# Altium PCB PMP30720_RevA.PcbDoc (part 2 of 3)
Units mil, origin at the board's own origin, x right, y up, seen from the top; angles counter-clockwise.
Board outline 4575 x 5400 mil, 4 copper layers (Top Layer, Signal Layer 1, Signal Layer 2, Bottom Layer), stack 61.6 mil thick; 223 components, 107 nets, 514 pads, 63 vias.
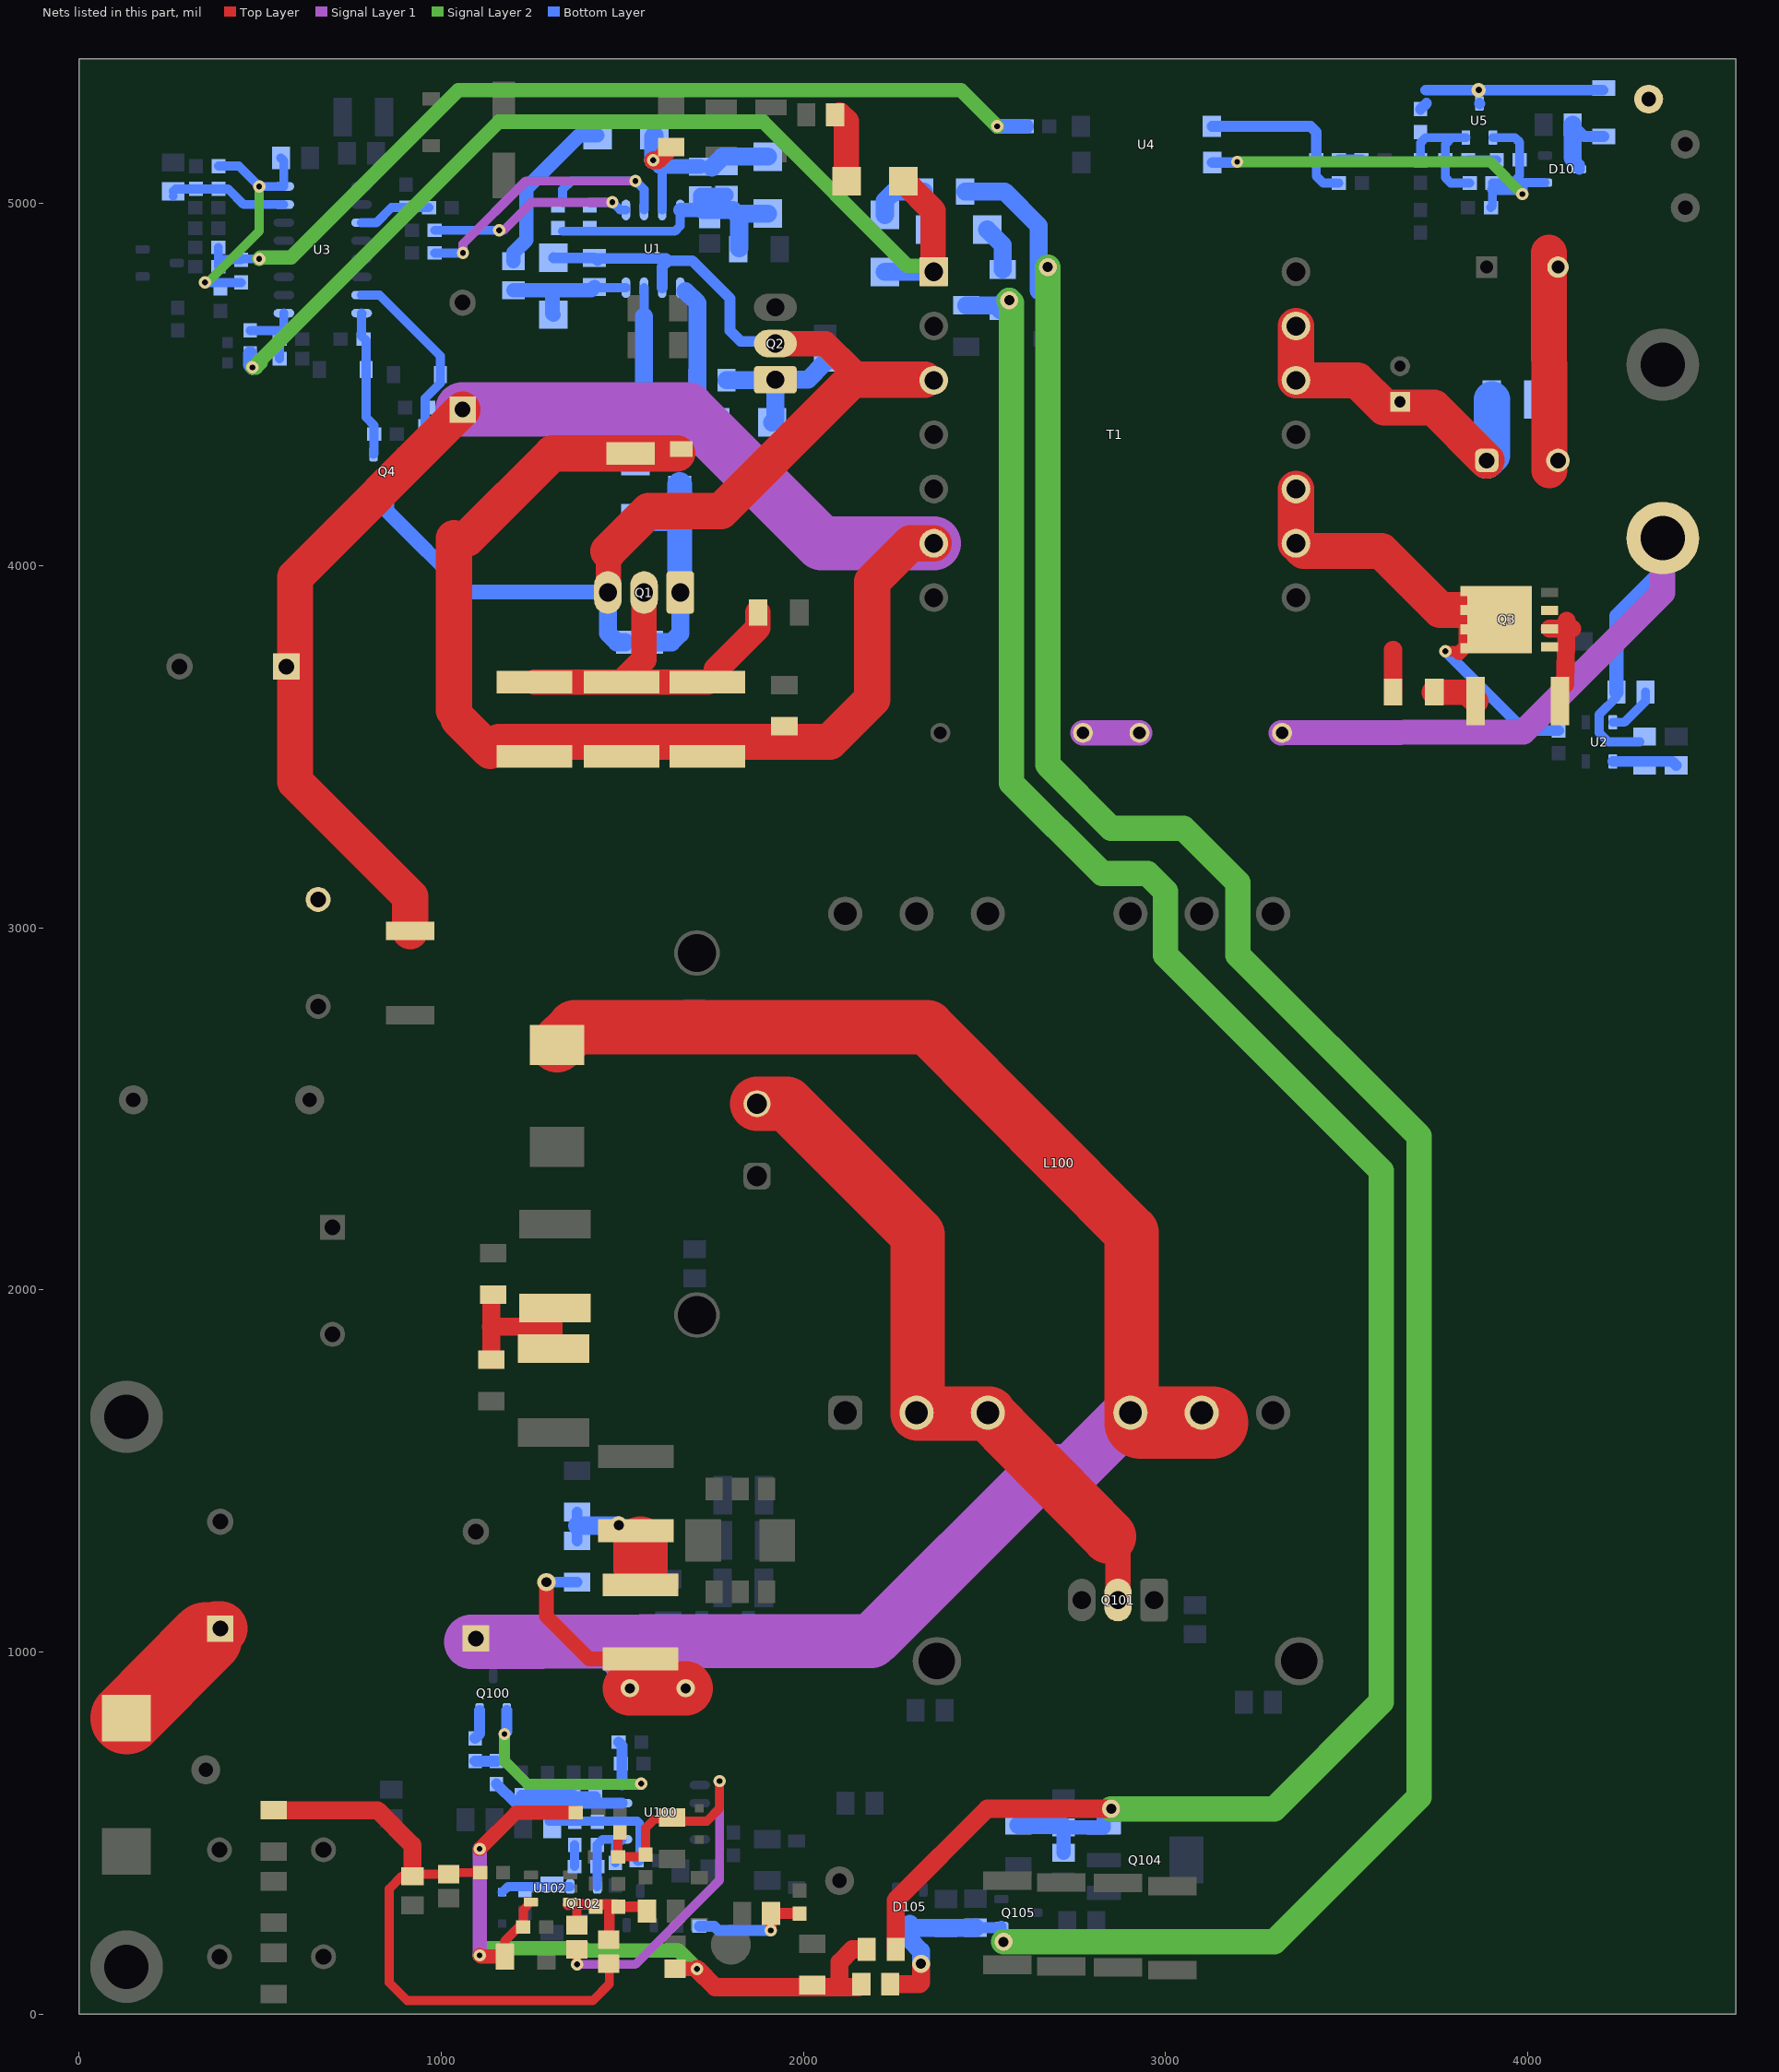
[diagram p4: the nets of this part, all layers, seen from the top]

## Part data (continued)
C102 C104 C124: library part Capacitor, "CAP, CERM, xxxF, xxV, [TempCo], xx%, [PackageReference]", Alternate Manufacturer=-, Manufacturer="Used in BOM report"
C103 C106: "CAP, CERM, 2.2 µF, 250 V,+/- 20%, X7R, AEC-Q200 Grade 1, 6x5x5mm", Cap_Case=2220, Manufacturer=TDK, Supplier Part Number 1=445-4110-1-ND, TempCo=X7R, Tolerance_%=20, Value2=250V, ValueDisplayed=2.2µF
C105: library part CMP-0010026-1, "CAP, AL, 47 uF, 400 V, +/- 20%, TH", Cap_Case=18x20, Manufacturer=Panasonic, Supplier Part Number 1=P13667-ND, Tolerance_%=20%, Value1=Unknown, Value2=400V, ValueDisplayed=47uF
C107: "CAP, CERM, 0.1 µF, 50 V,+/- 10%, X7R, 0603", Cap_Case=0603, Manufacturer=MuRata, Supplier Part Number 1=490-4779-1-ND, TempCo=X7R, Tolerance_%=10, Value1="0.02 ohm", Value2=50V, ValueDisplayed=0.1µF
C108: "CAP, CERM, 2.2 µF, 25 V,+/- 10%, X7R, 1206", Cap_Case=1206, Manufacturer=MuRata, Supplier Part Number 1=490-3368-1-ND, TempCo=X7R, Tolerance_%=10, Value2=25V, ValueDisplayed=2.2µF
C109: library part C0603C103J5RACTU, "CAP, CERM, 0.01 µF, 50 V,+/- 5%, X7R, 0603", Cap_Case=0603, Manufacturer=Kemet, Supplier Part Number 1=399-1092-1-ND, TempCo=X7R, Tolerance_%=5, Value2=50V
C110: "CAP, CERM, 0.47 µF, 50 V,+/- 10%, X7R, 0603", Cap_Case=0603, Manufacturer=TDK, Supplier Part Number 1=445-5952-1-ND, TempCo=X7R, Tolerance_%=10, Value1="0.010974 ohm", Value2=50V, ValueDisplayed=0.47µF
C111: "CAP, CERM, 47 pF, 50 V,+/- 5%, C0G/NP0, 0603", Cap_Case=0603, Manufacturer=MuRata, Supplier Part Number 1=490-1419-1-ND, TempCo=C0G/NP0, Tolerance_%=5, Value2=50V, ValueDisplayed=47pF
C112: "CAP, CERM, 470 pF, 50 V,+/- 5%, C0G/NP0, 0603", Cap_Case=0603, Manufacturer=MuRata, Supplier Part Number 1=490-1443-1-ND, TempCo=C0G/NP0, Tolerance_%=5, Value2=50V, ValueDisplayed=470pF
C113: "CAP, CERM, 1 µF, 16 V,+/- 10%, X7R, 0805", Cap_Case=0805, Manufacturer=MuRata, Supplier Part Number 1=490-1691-1-ND, TempCo=X7R, Tolerance_%=10, Value1="0.003 ohm", Value2=16V, ValueDisplayed=1µF
C114: "CAP, CERM, 4.7 µF, 25 V,+/- 10%, X7R, 1206", Cap_Case=1206, Manufacturer=MuRata, Supplier Part Number 1=490-1809-1-ND, TempCo=X7R, Tolerance_%=10, Value2=25V, ValueDisplayed=4.7µF
C116: "CAP, CERM, 0.1 µF, 50 V,+/- 10%, X7R, 0603", Cap_Case=0603, Manufacturer=MuRata, Supplier Part Number 1=490-1519-1-ND, TempCo=X7R, Tolerance_%=10, Value2=50V, ValueDisplayed=0.1µF
C120: "CAP, CERM, 0.22 µF, 50 V,+/- 10%, X7R, 0805", Cap_Case=0805, Manufacturer=MuRata, Supplier Part Number 1=490-1670-1-ND, TempCo=X7R, Tolerance_%=10, Value2=50V, ValueDisplayed=0.22µF
C121: library part Capacitor, "CAP, CERM, xxxF, xxV, [TempCo], xx%, [PackageReference]", Alternate Manufacturer=-
D1: "Diode, Ultrafast, 600 V, 1 A, AEC-Q101, SMA", Manufacturer="ON Semiconductor", Supplier Part Number 1=MURA160T3GOSCT-ND, Value1=1A, Value2=1.05V
D2 D5: "Diode, Schottky, 30 V, 1 A, SMA", Manufacturer="Diodes Inc.", Supplier Part Number 1=B130-FDICT-ND, Value1=1A, Value2=0.5V
D3 D4: "Diode, Zener, 18 V, 1 W, AEC-Q101, SMA", Manufacturer="Diodes Inc.", Power_W=1, Supplier Part Number 1=SMAZ18-FDICT-ND, Value1=1W
D6 D7: "Diode, Ultrafast, 200 V, 1 A, SMA", Manufacturer="Diodes Inc.", Supplier Part Number 1=ES1D-FDICT-ND, Value1=1A, Value2=0.92V
D8: "Diode, Schottky, 200 V, 1 A, SMA", Manufacturer="Micro Commercial Components", Supplier Part Number 1=SS1200-LTPMSCT-ND, Value1=1A, Value2=0.92V
D9: "Diode, Zener, 27 V, 500 mW, SOD-123", Manufacturer="Diodes Inc.", Power_W=0.5, Supplier Part Number 1=MMSZ5254B-FDICT-ND, Value1=0.5W
D10: "Diode, Schottky, 30 V, 0.2 A, SOT-23", Manufacturer="Diodes Inc.", Supplier Part Number 1=BAT54S-FDICT-ND, Value1=0.2A, Value2=0.65V
D100: "Diode, Switching, 800 V, 3 A, SMC", Manufacturer=Vishay-Semiconductor, Supplier Part Number 1=RS3K-E3/9ATGICT-ND, Value1=3A, Value2=1.3V
D101: library part APT20SCD65K, "Diode, Schottky, 600 V,", Manufacturer=Microsemi
D102 Dz2: "Diode, Zener, 18 V, 500 mW, SOD-123", Manufacturer="Diodes Inc.", Power_W=0.5, Supplier Part Number 1=MMSZ5248B-FDICT-ND, Value1=0.5W
D103: "Diode, Schottky, 30 V, 0.2 A, SOD-323", Manufacturer="ON Semiconductor", Supplier Part Number 1=BAT54HT1OSCT-ND, Value1=0.2A, Value2=0.35V
D104: "Diode, Schottky, 20 V, 0.5 A, SOD-123", Manufacturer="ON Semiconductor", Supplier Part Number 1=MBR0520LT1GOSCT-ND, Value1=0.5A, Value2=0.385V
D105: "Diode, Zener, 18 V, 225 mW, SOT-23", Manufacturer="ON Semiconductor", Power_W=0.225, Supplier Part Number 1=MMBZ5248BLT1GOSCT-ND, Value1=0.225W
D106: "Diode, Zener, 10 V, 200 mW, SOD-323", Manufacturer="Diodes Inc.", Power_W=0.2, Supplier Part Number 1=MMSZ5240BS-FDICT-ND, Value1=0.2W
D107: "Diode, Zener, 4.7 V, 500 mW, SOD-123", Manufacturer="ON Semiconductor", Power_W=0.5, Supplier Part Number 1=MMSZ4688T1GOSCT-ND, Value1=0.5W
"DANGER HIGH VOLTAGE1" "High Voltage100": library part IEC_HighVoltage, "IEC 61010-1 High Voltage Warning"
DZ1: "Diode, Zener, 24 V, 500 mW, SOD-123", Manufacturer="Diodes Inc.", Power_W=0.5, Supplier Part Number 1=MMSZ5252B-FDICT-ND, Value1=0.5W
F100: library part 0443003.DR, "Fuse, 5 A, 250VAC/VDC, SMD", Irating_A=5, Manufacturer=Littelfuse, Supplier Part Number 1=F2910CT-ND
H100: "HEATSINK TO-220 W/PINS 1\" TALL", Manufacturer=Aavid, Supplier Part Number 1=HS351-ND
H101: "Heatsink, TO-220, TO-218, TO-247", Manufacturer=Ohmite, Supplier Part Number 1=FA-T220-64E-ND
L1: library part CMP-0064179-1, "Inductor, Unshielded Drum Core, Ferrite, 1 uH, 8 A, 0.006 ohm, TH", Manufacturer="Wurth Elektronik", Supplier Part Number 1=732-2565-ND, Value1="0.006 ohm", Value2=8A, ValueDisplayed=SHORT
L100: library part CMP-0086236-1, "Inductor, 300 µH, 0.065 ohm, TH", Manufacturer="Wurth Elektronik", Value1="0.065 ohm", Value2=A, ValueDisplayed=300µH
Q1 Q2: library part MOSFET_N_D2G1S3, "MOSFET, N-CH, 650V, xxxA, [PackageReference]", Alternate Manufacturer=-, Manufacturer=Infineon
Q3: library part CMP-0079124-1, "MOSFET, N-CH, 200 V, PG-TDSON-8", Alternate Manufacturer=None, PartNumber=SiR616DP, Supplier Part Number 1=SiR610DP, Value1="? ohm"
Q4: "MOSFET, N-CH, 600 V, 0.021 A, AEC-Q101, SOT-23", Alternate Manufacturer=None, Manufacturer="Infineon Technologies", Supplier Part Number 1="BSS126 H6906CT-ND", Value1="? ohm", Value2="1.4 nC"
Q5: library part CMP-0000769-1, "MOSFET, N-CH, 60 V, 0.17 A, SOT-23", Alternate Manufacturer=None, Manufacturer="Diodes Inc.", Supplier Part Number 1=2N7002-FDICT-ND, Value1=7, Value2="223 nC"
Q100 Q103: library part "MMBT3904-7-F, Diodes Inc.", "Transistor, NPN, 40 V, 0.2 A, SOT-23", Manufacturer="Diodes Inc.", Supplier Part Number 1=MMBT3904-FDICT-ND, Value1="0.2 A", Value2=400
Q101: library part CMP-0001173-3, "MOSFET, N-CH, 600 V, 25 A, TO-220AB", Alternate Manufacturer=None, Manufacturer="Infineon Technologies", Supplier Part Number 1=IPP60R125C, Value2="53 nC"
Q102: library part "MMBT2907ALT1G, ON Semiconductor", "Transistor, PNP, 60 V, 0.6 A, SOT-23", Manufacturer="ON Semiconductor", Supplier Part Number 1=MMBT2907ALT1GOSCT-ND, Value1="0.6 A"
Q104: library part CMP-0086195-1, "MOSFET, N-CH, Depletion Mode, 600 V, 0.1 A, SOT-223", Alternate Manufacturer=None, Manufacturer=IXYS, Value1="? ohm", Value2="? nC"
Q105: "MOSFET, N-CH, 60 V, 0.17 A, SOT-23", Alternate Manufacturer=None, Manufacturer="Diodes Inc.", Supplier Part Number 1=2N7002-FDICT-ND, Value1="7.5 ohm", Value2="223 nC"
R1 R2: "RES, 383 k, 1%, 0.25 W, 1206", Manufacturer=Vishay-Dale, Power_W=0.25, Supplier Part Number 1=541-383KFCT-ND, TempCo="100 ppm/C", Tolerance_%=1, Value1=1%, Value2=0.25W, Value_Code=383k
R3 R20 R24 R110: "RES, 10, 5%, 0.125 W, 0805", Manufacturer=Vishay-Dale, Power_W=0.125, Supplier Part Number 1=541-10ACT-ND, TempCo="200 ppm/C", Tolerance_%=5, Value1=5%, Value2=0.125W, Value_Code=10R0, ValueDisplayed=10
R4: "RES, 100, 5%, 0.25 W, 1206", Manufacturer=Vishay-Dale, Power_W=0.25, Supplier Part Number 1=541-100ECT-ND, TempCo="200 ppm/C", Tolerance_%=5, Value1=5%, Value2=0.25W, Value_Code=100R, ValueDisplayed=100
R5 R8: "RES, 4.99 k, 1%, 0.125 W, 0805", Manufacturer=Vishay-Dale, Power_W=0.125, Supplier Part Number 1=541-4.99KCCT-ND, TempCo="100 ppm/C", Tolerance_%=1, Value1=1%, Value2=0.125W, Value_Code=4k99, ValueDisplayed=4.99k
R6 R7: "RES, 15.0, 1%, 0.125 W, 0805", Manufacturer=Vishay-Dale, Power_W=0.125, Supplier Part Number 1=541-15.0CCT-ND, TempCo="100 ppm/C", Tolerance_%=1, Value1=1%, Value2=0.125W, Value_Code=15R0, ValueDisplayed=15.0
R9 R40 R102 R104 R151 R152: library part Resistor, "RES, xxx ohm, x%, xW, [PackageReference]", Alternate Manufacturer=-, Manufacturer="Used in BOM report"
R10 R132: "RES, 0, 5%, 0.25 W, 1206", Manufacturer=Vishay-Dale, Power_W=0.25, Supplier Part Number 1=541-0.0ECT-ND, TempCo="200 ppm/C", Tolerance_%=5, Value1=5%, Value2=0.25W, Value_Code=0000, ValueDisplayed=0
R11 R12 R23: "RES, 49.9, 1%, 0.1 W, 0603", Manufacturer=Vishay-Dale, Power_W=0.1, Supplier Part Number 1=541-49.9HCT-ND, TempCo="100 ppm/C", Tolerance_%=1, Value1=1%, Value2=0.1W, Value_Code=49R9, ValueDisplayed=49.9
R13: "RES, 0.27, 1%, 0.25 W, 1206", Manufacturer=Panasonic, Power_W=0.25, Supplier Part Number 1=P.27RCT-ND, TempCo="250 ppm/C", Tolerance_%=1, Value1=1%, Value2=0.25W, Value_Code=R270, ValueDisplayed=0.27
R14: "RES, 0.33, 1%, 0.25 W, 1206", Manufacturer=Panasonic, Power_W=0.25, Supplier Part Number 1=P.33RCT-ND, TempCo="250 ppm/C", Tolerance_%=1, Value1=1%, Value2=0.25W, Value_Code=R330, ValueDisplayed=0.33
R15: "RES, 3.3, 5%, 1 W, AEC-Q200 Grade 0, 2512", Manufacturer=Vishay-Dale, Power_W=1, Supplier Part Number 1=541-3.3XCT-ND, TempCo="200 ppm/C", Tolerance_%=5, Value1=5%, Value2=1W, Value_Code=3R30, ValueDisplayed=3.3
R16: "RES, 499, 1%, 0.25 W, 1206", Manufacturer=Vishay-Dale, Power_W=0.25, Supplier Part Number 1=541-499FCT-ND, TempCo="100 ppm/C", Tolerance_%=1, Value1=1%, Value2=0.25W, Value_Code=499R, ValueDisplayed=499
R17: "RES, 10.0, 1%, 0.25 W, 1206", Manufacturer=Vishay-Dale, Power_W=0.25, Supplier Part Number 1=541-10.0FCT-ND, TempCo="100 ppm/C", Tolerance_%=1, Value1=1%, Value2=0.25W, Value_Code=10R0, ValueDisplayed=10.0
R18: "RES, 10.0, 1%, 0.125 W, 0805", Manufacturer=Vishay-Dale, Power_W=0.125, Supplier Part Number 1=541-10.0CCT-ND, TempCo="100 ppm/C", Tolerance_%=1, Value1=1%, Value2=0.125W, Value_Code=10R0, ValueDisplayed=10.0
R19: "RES, 10.0, 1%, 0.1 W, 0603", Manufacturer=Vishay-Dale, Power_W=0.1, Supplier Part Number 1=541-10.0HCT-ND, TempCo="100 ppm/C", Tolerance_%=1, Value1=1%, Value2=0.1W, Value_Code=10R0, ValueDisplayed=10.0
R21: "RES, 41.2 k, 1%, 0.1 W, 0603", Manufacturer=Vishay-Dale, Power_W=0.1, Supplier Part Number 1=541-41.2KHCT-ND, TempCo="100 ppm/C", Tolerance_%=1, Value1=1%, Value2=0.1W, Value_Code=41k2, ValueDisplayed=41.2k
R22 R109: "RES, 10.0 k, 1%, 0.1 W, 0603", Manufacturer=Vishay-Dale, Power_W=0.1, Supplier Part Number 1=541-10.0KHCT-ND, TempCo="100 ppm/C", Tolerance_%=1, Value1=1%, Value2=0.1W, Value_Code=10k0, ValueDisplayed=10.0k
R25 R115 R119 R144 R147: "RES, 0, 5%, 0.1 W, 0603", Manufacturer=Vishay-Dale, Power_W=0.1, Supplier Part Number 1=541-0.0GCT-ND, TempCo="200 ppm/C", Tolerance_%=5, Value1=5%, Value2=0.1W, Value_Code=0000, ValueDisplayed=0
R26: "RES, 1.00 M, 1%, 0.1 W, 0603", Manufacturer=Vishay-Dale, Power_W=0.1, Supplier Part Number 1=541-1.00MHCT-ND, TempCo="100 ppm/C", Tolerance_%=1, Value1=1%, Value2=0.1W, Value_Code=1M00, ValueDisplayed=1.00M
R27: "RES, 196 k, 1%, 0.1 W, 0603", Manufacturer=Vishay-Dale, Power_W=0.1, Supplier Part Number 1=541-196KHCT-ND, TempCo="100 ppm/C", Tolerance_%=1, Value1=1%, Value2=0.1W, Value_Code=196k
R28 R29: "RES, 1.00 k, 1%, 0.1 W, 0603", Manufacturer=Vishay-Dale, Power_W=0.1, Supplier Part Number 1=541-1.00KHCT-ND, TempCo="100 ppm/C", Tolerance_%=1, Value1=1%, Value2=0.1W, Value_Code=1k00, ValueDisplayed=1.00k
R30: "RES, 34.0 k, 1%, 0.1 W, 0603", Manufacturer=Vishay-Dale, Power_W=0.1, Supplier Part Number 1=541-34.0KHCT-ND, TempCo="100 ppm/C", Tolerance_%=1, Value1=1%, Value2=0.1W, Value_Code=34k0, ValueDisplayed=34.0k
R31: "RES, 12.1 k, 1%, 0.1 W, 0603", Manufacturer="Yageo America", Power_W=0.1, Supplier Part Number 1=311-12.1KHRCT-ND, TempCo="200 ppm/C", Tolerance_%=1, Value1=1%, Value2=0.1W, Value_Code=12k1, ValueDisplayed=12.1k
R32 R36: "RES, 150 k, 1%, 0.1 W, 0603", Manufacturer=Vishay-Dale, Power_W=0.1, Supplier Part Number 1=541-150KHCT-ND, TempCo="100 ppm/C", Tolerance_%=1, Value1=1%, Value2=0.1W, Value_Code=150k
R33: "RES, 15.0 k, 1%, 0.1 W, 0603", Manufacturer=Vishay-Dale, Power_W=0.1, Supplier Part Number 1=541-15.0KHCT-ND, TempCo="100 ppm/C", Tolerance_%=1, Value1=1%, Value2=0.1W, Value_Code=15k0, ValueDisplayed=15.0k
R34: "RES, 121, 1%, 0.1 W, 0603", Manufacturer=Vishay-Dale, Power_W=0.1, Supplier Part Number 1=541-121HCT-ND, TempCo="100 ppm/C", Tolerance_%=1, Value1=1%, Value2=0.1W, Value_Code=121R, ValueDisplayed=121
R35: "RES, 604 k, 1%, 0.1 W, 0603", Manufacturer=Vishay-Dale, Power_W=0.1, Supplier Part Number 1=541-604KHCT-ND, TempCo="100 ppm/C", Tolerance_%=1, Value1=1%, Value2=0.1W, Value_Code=604k
R37 R121 R138: "RES, 249 k, 1%, 0.1 W, 0603", Manufacturer=Vishay-Dale, Power_W=0.1, Supplier Part Number 1=541-249KHCT-ND, TempCo="100 ppm/C", Tolerance_%=1, Value1=1%, Value2=0.1W, Value_Code=249k
R38: "RES, 124 k, 1%, 0.1 W, 0603", Manufacturer=Vishay-Dale, Power_W=0.1, Supplier Part Number 1=541-124KHCT-ND, TempCo="100 ppm/C", Tolerance_%=1, Value1=1%, Value2=0.1W, Value_Code=124k
R39: "RES, 47.5 k, 1%, 0.1 W, 0603", Manufacturer=Vishay-Dale, Power_W=0.1, Supplier Part Number 1=541-47.5KHCT-ND, TempCo="100 ppm/C", Tolerance_%=1, Value1=1%, Value2=0.1W, Value_Code=47k5, ValueDisplayed=47.5k
R41: "RES, 21.5 k, 1%, 0.1 W, 0603", Manufacturer=Vishay-Dale, Power_W=0.1, Supplier Part Number 1=541-21.5KHCT-ND, TempCo="100 ppm/C", Tolerance_%=1, Value1=1%, Value2=0.1W, Value_Code=21k5, ValueDisplayed=21.5k
R42: "RES, 100 k, 1%, 0.125 W, 0805", Manufacturer=Vishay-Dale, Power_W=0.125, Supplier Part Number 1=541-100KCCT-ND, TempCo="100 ppm/C", Tolerance_%=1, Value1=1%, Value2=0.125W, Value_Code=100k
R100 R101 R116 R117 R134 R146: "RES, 0, 5%, 0.125 W, 0805", Manufacturer=Vishay-Dale, Power_W=0.125, Supplier Part Number 1=541-0.0ACT-ND, TempCo="200 ppm/C", Tolerance_%=5, Value1=5%, Value2=0.125W, Value_Code=0000, ValueDisplayed=0
R103 R106: "RES, 499 k, 1%, 0.25 W, 1206", Manufacturer=Vishay-Dale, Power_W=0.25, Supplier Part Number 1=541-499KFCT-ND, TempCo="100 ppm/C", Tolerance_%=1, Value1=1%, Value2=0.25W, Value_Code=499k
R105: "RES, 49.9, 1%, 0.125 W, 0805", Manufacturer=Vishay-Dale, Power_W=0.125, Supplier Part Number 1=541-49.9CCT-ND, TempCo="100 ppm/C", Tolerance_%=1, Value1=1%, Value2=0.125W, Value_Code=49R9, ValueDisplayed=49.9
R107 R108: "RES, 374 k, 1%, 0.125 W, 0805", Manufacturer=Vishay-Dale, Power_W=0.125, Supplier Part Number 1=541-374KCCT-ND, TempCo="100 ppm/C", Tolerance_%=1, Value1=1%, Value2=0.125W, Value_Code=374k
R111: "RES, 30.1 k, 1%, 0.1 W, 0603", Manufacturer=Vishay-Dale, Power_W=0.1, Supplier Part Number 1=541-30.1KHCT-ND, TempCo="100 ppm/C", Tolerance_%=1, Value1=1%, Value2=0.1W, Value_Code=30k1, ValueDisplayed=30.1k
R112 R118 R123 R130: "RES, 4.7 k, 5%, 1 W, AEC-Q200 Grade 0, 2512", Manufacturer=Vishay-Dale, Power_W=1, Supplier Part Number 1=541-4.7KXCT-ND, TempCo="200 ppm/C", Tolerance_%=5, Value1=5%, Value2=1W, Value_Code=4k70, ValueDisplayed=4.7k
R113 R145: "RES, 10.0 k, 1%, 0.125 W, 0805", Manufacturer=Vishay-Dale, Power_W=0.125, Supplier Part Number 1=541-10.0KCCT-ND, TempCo="100 ppm/C", Tolerance_%=1, Value1=1%, Value2=0.125W, Value_Code=10k0, ValueDisplayed=10.0k
R114: "RES, 6.98 k, 1%, 0.1 W, 0603", Manufacturer=Vishay-Dale, Power_W=0.1, Supplier Part Number 1=541-6.98KHCT-ND, TempCo="100 ppm/C", Tolerance_%=1, Value1=1%, Value2=0.1W, Value_Code=6k98, ValueDisplayed=6.98k
R120: library part CRCW06032K21FKEA, "RES, 2.21 k, 1%, 0.1 W, 0603", Manufacturer=Vishay-Dale, Power_W=0.1, Supplier Part Number 1=541-2.21KHCT-ND, TempCo="100 ppm/C", Tolerance_%=1, Value1=1%, Value2=0.1W, Value_Code=2k21
R122: "RES, 19.1 k, 1%, 0.1 W, 0603", Manufacturer=Vishay-Dale, Power_W=0.1, Supplier Part Number 1=541-19.1KHCT-ND, TempCo="100 ppm/C", Tolerance_%=1, Value1=1%, Value2=0.1W, Value_Code=19k1, ValueDisplayed=19.1k
R124: "RES, 2.21 k, 1%, 0.1 W, 0603", Manufacturer=Vishay-Dale, Power_W=0.1, Supplier Part Number 1=541-2.21KHCT-ND, TempCo="100 ppm/C", Tolerance_%=1, Value1=1%, Value2=0.1W, Value_Code=2k21, ValueDisplayed=2.21k
R125: library part CRCW060337K4FKEA, "RES, 37.4 k, 1%, 0.1 W, 0603", Manufacturer=Vishay-Dale, Power_W=0.1, Supplier Part Number 1=541-37.4KHCT-ND, TempCo="100 ppm/C", Tolerance_%=1, Value1=1%, Value2=0.1W, Value_Code=37k4
R126: "RES, 4.99, 1%, 0.25 W, 1206", Manufacturer=Vishay-Dale, Power_W=0.25, Supplier Part Number 1=541-4.99FFCT-ND, TempCo="100 ppm/C", Tolerance_%=1, Value1=1%, Value2=0.25W, Value_Code=4R99, ValueDisplayed=4.99
R127 R128 R129: library part Resistor, "RES, 0.18 ohm, 1%, 500mW, current sense [PackageReference]", Alternate Manufacturer=-, Manufacturer="Panasonic Electronic Components"
R131 R133: "RES, 200 k, 5%, 0.125 W, 0805", Manufacturer=Vishay-Dale, Power_W=0.125, Supplier Part Number 1=541-200KACT-ND, TempCo="200 ppm/C", Tolerance_%=5, Value1=5%, Value2=0.125W, Value_Code=200k
R135: library part CRCW08050000Z0EA, "RES, 0, 5%, 0.125 W, 0805", Manufacturer=Vishay-Dale, Power_W=0.125, Supplier Part Number 1=541-0.0ACT-ND, TempCo="200 ppm/C", Tolerance_%=5, Value1=5%, Value2=0.125W, Value_Code=0000
R136: "RES, 0, 5%, 0.333 W, 0805", Manufacturer=Vishay-Dale, Power_W=0.333, Supplier Part Number 1=541-0.0TBCT-ND, TempCo="200 ppm/C", Tolerance_%=5, Value1=5%, Value2=0.333W, Value_Code=0000, ValueDisplayed=0
R137 R140: "RES, 3.92 M, 1%, 0.25 W, 1206", Manufacturer=Vishay-Dale, Power_W=0.25, Supplier Part Number 1=541-3.92MFCT-ND, TempCo="100 ppm/C", Tolerance_%=1, Value1=1%, Value2=0.25W, Value_Code=3M92, ValueDisplayed=3.92M
R139 R142: library part Resistor, "RES, xxx ohm, x%, xW, [PackageReference]", Alternate Manufacturer=-
R141 R149: "RES, 499 k, 1%, 0.1 W, 0603", Manufacturer=Vishay-Dale, Power_W=0.1, Supplier Part Number 1=541-499KHCT-ND, TempCo="100 ppm/C", Tolerance_%=1, Value1=1%, Value2=0.1W, Value_Code=499k
R143: "RES, 499 k, 1%, 0.125 W, 0805", Manufacturer=Vishay-Dale, Power_W=0.125, Supplier Part Number 1=541-499KCCT-ND, TempCo="100 ppm/C", Tolerance_%=1, Value1=1%, Value2=0.125W, Value_Code=499k
R148: "RES, 100 k, 1%, 0.1 W, 0603", Manufacturer=Vishay-Dale, Power_W=0.1, Supplier Part Number 1=541-100KHCT-ND, TempCo="100 ppm/C", Tolerance_%=1, Value1=1%, Value2=0.1W, Value_Code=100k
R150: "RES, 402 k, 1%, 0.125 W, 0805", Manufacturer=Vishay-Dale, Power_W=0.125, Supplier Part Number 1=541-402KCCT-ND, TempCo="100 ppm/C", Tolerance_%=1, Value1=1%, Value2=0.125W, Value_Code=402k
RF1: "RES, 0, 5%, 1 W, AEC-Q200 Grade 0, 2512", Manufacturer=Vishay-Dale, Power_W=1, Supplier Part Number 1=541-0.0XCT-ND, TempCo=ppm/C, Tolerance_%=5, Value1=5%, Value2=1W, Value_Code=0000, ValueDisplayed=0
RT1: library part B57237S0479M000, "Thermistor NTC, 5 ohm", Manufacturer=TDK, Power_W=3.1, Supplier Part Number 1=495-2099-ND, Tolerance_%=20
RT2: "Thermistor NTC, 47.0k ohm, 1%, 0603", Manufacturer=MuRata, Power_W=0.1, Supplier Part Number 1=NCP18WB473F10RB-ND, Tolerance_%=1
RT100 RT101: library part B57237S229M, "Thermistor NTC, 2.2 ohm, 20%, 15x7mm", Manufacturer=TDK, Power_W=3.1, Supplier Part Number 1=495-3055-ND, Tolerance_%=20
T1: library part CMP-0086589-1, "PTH_TRANSFORMER_14", Manufacturer="Wurth Electronics"
TP1 TP2 TP5 TP6: "Test Point, Miniature, Red, TH", Color=Red, Manufacturer=Keystone, Supplier Part Number 1=36-5000-ND
TP3 TP4 TP100 TP102: library part 1503-2, "Terminal, Turret, TH, Double", Manufacturer=Keystone, Supplier Part Number 1=36-1503-2-ND
TP7: "Test Point, Miniature, Black, TH", Color=Black, Manufacturer=Keystone, Supplier Part Number 1=36-5001-ND
TP101: library part CMP-0055137-1, "Test Point, Miniature, Red, TH", Color=Red, Manufacturer=Keystone, Supplier Part Number 1=36-5000-ND
TP103: library part CMP-0055138-1, "Test Point, Miniature, Black, TH", Color=Black, Manufacturer=Keystone, Supplier Part Number 1=36-5001-ND
TP104: "PC Test Point, SMT", Manufacturer=Mill-Max, Supplier Part Number 1=ED1088CT-ND
U1: library part CMP-0013005-1, "620-V High-Side Low-Side Gate Driver with 2.5A Peak Output and RobustDrive, D0008A (SOIC-8)", Alternate Manufacturer="Texas Instruments", Alternate PartNumber=UCC27712D
U2: library part CMP-0013050-3, "High-Frequency Multi-Mode Synchronous Rectifier Controller, DBV0005A (SOT-23-5)", Alternate Manufacturer="Texas Instruments", Alternate PartNumber=UCC24612-1DBVT
U3: library part CMP-0013027-1, "Active-Clamp Flyback Controller, D0016A (SOIC-16)", Alternate Manufacturer="Texas Instruments", Alternate PartNumber=UCC28780D
U4: "Optocoupler, 5 kV, 80-160% CTR, SMT", Manufacturer="Fairchild Semiconductor", Supplier Part Number 1=FOD817AS-ND, Voltage_Isolation_Vrms=5000V
U5: library part CMP-0066200-1, "2.5V Low Iq Adjustable Precision Shunt Regulator, DBZ0003A (SOT-23-3)", Alternate Manufacturer="Texas Instruments", Alternate PartNumber=ATL431BQDBZT
U100: "BiCMOS Low Current 8 Pin PWM Current Mode Controller, D0008A (SOIC-8)", Alternate Manufacturer="Texas Instruments", Alternate PartNumber=UCC28C42D
U101: library part CMP-0078944-1, "Transformer, 500 uH, SMD", Manufacturer="Wurth Elektronik", Supplier Part Number 1=732-3282-1-ND, ValueDisplayed=500µH
U102: library part CMP-0080757-2, "40 V, microPower, Push-Pull Comparator with Shutdown, DBV0006A (SOT-23-6)", Alternate Manufacturer="Texas Instruments"

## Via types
v1: diameter 34, hole 16, Top Layer to Bottom Layer, 36 vias
v2: diameter 50, hole 28, Top Layer to Bottom Layer, 21 vias
v3: diameter 40, hole 18, Top Layer to Bottom Layer, 5 vias
v4: diameter 32, hole 16, Top Layer to Bottom Layer, 1 vias

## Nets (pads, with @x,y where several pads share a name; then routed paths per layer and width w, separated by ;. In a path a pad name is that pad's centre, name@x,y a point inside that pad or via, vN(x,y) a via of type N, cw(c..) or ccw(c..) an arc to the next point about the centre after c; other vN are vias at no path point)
AUX_ACF_1: C18.1 C120.1 D105.3 Q105.1 R16.1 R135.2 R143.2 | length 7066.4
  Top Layer w50: R135.2@2240,83.12 2320.62,83.12 2325,87.5 v2(2325,139.32)
  Signal Layer 2 w70: v2(2552.87,200.07) 3300.07,200.07 3700,600 3700,2425 3200,2925 3200,3125 3050,3275 2850,3275 2675,3450 v2(2675,4824.48)
  Bottom Layer w30: R143.2@2475,239.04 2542.43,239.04 Q105.1@2546.51,243.12 2546.51,206.43 v2(2552.87,200.07)
  Bottom Layer w50: v2(2325,139.32) 2325,174.19 2293.75,205.44 D105.3@2293.75,249.13 2304.92,237.96 C120.1@2393.75,237.96 2473.92,237.96 R143.2@2475,239.04 ; R16.1@2446.86,5033.09 2555.6,5033.09 2650,4938.69 C18.1@2650,4760.14
AUX_ACF_2: C17.1 C119.1 Q104.3 R17.1 R133.1 R134.2 R136.2 | length 6572.4
  Top Layer w50: R134.2@2255,179.04 2255,314.69 2507.62,567.31 v2(2850,567.31)
  Signal Layer 2 w70: v2(2568.65,4732.67) 2575,4726.32 2575,3400 2825,3150 2950,3150 3000,3100 3000,2925 3595.72,2329.28 3595.72,862.78 3300.25,567.31 v2(2850,567.31)
  Bottom Layer w40: R133.1@2718.75,446.25 R136.2@2718.75,516.25 2718.87,516.13 Q104.3@2829.58,516.13 2829.58,546.89 v2(2850,567.31)
  Bottom Layer w50: C17.1@2450,4718.87 2535.01,4718.87 R17.1@2550,4703.88 ; C119.1@2593.75,522.05 2712.95,522.05 R136.2@2718.75,516.25
  Bottom Layer w70: R17.1@2550,4714.01 v2(2568.65,4732.67)
Disable: C122.1 R119.2 R146.2 | length 328.8
  Top Layer w30: v1(1910.28,231.25) 1910.62,231.59 R146.2@1910.62,278.44 1989.12,278.44 C122.1@1989.37,278.2
  Bottom Layer w30: R119.2@1712.52,243.02 1753.98,243.02 1765.75,231.25 v1(1910.28,231.25)
FB: C111.2 R108.1 R121.1 R122.2 U100.2 | length 365.3
  Bottom Layer w25: R108.1@1297.73,532.8 U100.2@1499.54,532.8 1541.49,532.8 1548.45,525.84 1548.45,423.64 1541.49,423.64 R122.2@1543.28,421.85
GND1: C13.2 C14.2 C15.2 C22.1 C24.2 C25.2 C39.2 Q3.1 Q3.2 Q3.3 R15.2 R41.1 TP4.1 TP7.1 U2.2 U5.3 | length 3445.8
  Top Layer w50: Q3.2@4060.02,3825.97 4122.22,3825.97 ; R15.2@4103.03,3672.57 4107.36,3847.57
  Top Layer w100: 4058.56,4863.47 4060.02,4263.47
  Signal Layer 1 w70: C22.1@3319.49,3538.47 3987.53,3540.85 4372.64,3925.97 TP4.1@4372.64,4075.97
  Bottom Layer w25: C24.2@4245.14,3650.97 4245.14,3636.83 4197.64,3589.33 U2.2@4197.64,3567.6 4197.64,3538.47 4222.64,3513.47 C25.2@4310.14,3513.47
  Bottom Layer w30: R41.1@3704.13,5260.52 R41.1@3720.38,5276.77 ; 3718.19,5313.47 v3(3864.44,5313.47) C39.2@4207.14,5313.47 ; U5.3@3866.63,5276.77 U5.3@3867.44,5275.97
  Bottom Layer w40: C24.2@4245.14,3650.97 4245.14,3860.97 4372.64,3988.47 TP4.1@4372.64,4075.97
NetC1_1: C1.1 C2.1 C3.1 C4.1 C5.1 C6.1 C7.1 R1.2 RF1.2 RT1.2 T1.6 | length 6109.1
  Top Layer w100: RF1.2@914.3,2991.14 914.3,3085.7 596.54,3403.46 596.54,3968.54 C2.1@1059.04,4431.04 ; 1035.14,3600.97 1035.14,4075.97 ; 1047.64,3575.97 1135.14,3488.47 ; 1072.64,4075.97 1306.4,4309.73 C3.1@1522.64,4309.73 C4.1@1651.51,4309.73 ; 1160.14,3513.47 2072.64,3513.47 2189.93,3630.75 2189.93,3955.75 2295.95,4061.78 T1.6@2360.14,4061.78
  Signal Layer 1 w150: C2.1@1059.04,4431.04 1680.74,4431.04 2050,4061.78 T1.6@2360.14,4061.78
NetC5_2: C5.2 C6.2 C7.2 Q1.2 R2.1 | length 955.7
  Top Layer w70: C7.2@1257.95,3678.33 C6.2@1497.64,3678.33 ; Q1.2@1560.14,3925.97 1560.14,3740.83 C6.2@1497.64,3678.33 ; C5.2@1735.14,3678.33 C6.2@1497.64,3678.33 ; 1760.14,3713.47 1874.81,3828.14 R2.1@1874.81,3870.92
NetC8_1: C8.1 D3.1 R3.1 U1.8 | length 383.7
  Bottom Layer w25: C8.1@1422.64,4768.4 1423.29,4767.75 U1.8@1510.14,4767.75
  Bottom Layer w40: R3.1@1199.81,4760.97 1307.28,4760.97 ; D3.1@1310.14,4693.21 1307.28,4696.07 1307.28,4760.97 ; C8.1@1423.29,4769.51 1414.74,4760.97 1307.28,4760.97
NetC8_2: C8.2 D3.2 Q1.3 Q2.2 Q4.3 R5.1 T1.3 U1.6 | length 3245.7
  Top Layer w70: Q1.3@1460.14,3925.97 1461.67,3927.5 1461.67,4040 ; Q2.2@1922.64,4613.47 2060.14,4613.47 2135.14,4538.47 2135.14,4513.47
  Top Layer w100: 1461.67,4040 1572.64,4150.97 1772.64,4150.97 2135.14,4513.47 T1.3@2335.14,4513.47
  Bottom Layer w25: C8.2@1422.64,4848.4 C8.2@1431.63,4839.41
  Bottom Layer w30: D3.2@1310.14,4850.69 1311.32,4849.51 C8.2@1423.29,4849.51 ; C8.2@1422.64,4848.4 1621.08,4848.4 1627.2,4842.28 ; U1.6@1610.14,4767.75 1610.14,4825.23 1627.2,4842.28 ; Q2.2@1922.64,4613.47 1916.7,4619.41 1826.87,4619.41 1797.64,4648.64 1797.64,4737.89 1693.24,4842.28 1627.2,4842.28
  Bottom Layer w40: Q4.3@850.48,4213.07 850.48,4150.97 1074.3,3927.15 1458.96,3927.15 Q1.3@1460.14,3925.97
  Bottom Layer w50: Q1.3@1460.14,3925.97 1460.14,3813.47 1485.14,3788.47 R5.1@1507.64,3788.47
NetC9_1: C9.1 C10.1 D1.2 D4.1 R4.2 U1.3 | length 661.5
  Top Layer w50: v1(1585.14,5119.57) 1598.33,5119.57 R4.2@1635.14,5156.38
  Bottom Layer w25: D1.2@1588.88,5188.47 1610.14,5167.21 1610.14,5119.57 ; U1.3@1610.14,4982.32 1610.14,5102.28 ; C10.1@1722.64,5100.09 1747.64,5100.09
  Bottom Layer w40: v1(1585.14,5119.57) 1602.42,5102.28 1610.14,5102.28 C10.1@1715.04,5102.28
  Bottom Layer w50: v1(1585.14,5119.57) 1585.14,5184.73 D1.2@1588.88,5188.47 ; 1747.64,5100.09 1776.87,5129.32 D4.1@1901.58,5129.71
NetC9_2: C9.2 C10.2 C11.2 C12.2 D4.2 R9.1 R10.2 U1.4 | length 831.8
  Bottom Layer w25: C12.2@1335.14,4923.47 1645.14,4923.47 1660.14,4938.47 U1.4@1660.14,4982.32
  Bottom Layer w40: U1.4@1660.14,4982.32 1722.25,4982.32 1715.04,4989.52 C10.2@1715.04,5022.28 1716.22,5023.47 C9.2@1787.64,5023.47
  Bottom Layer w50: R9.1@1722.25,4982.32 1804.78,4982.32 1814.88,4972.23 D4.2@1901.58,4972.23 ; R10.2@1822.64,4876.78 1822.64,4971.84
NetC11_1: C11.1 R11.2 U1.1 | length 618.8
  Signal Layer 1 w25: v1@1172.64,4925.97 1250.14,5003.47 v1(1472.64,5003.47)
  Bottom Layer w25: R11.2@982.21,4925.97 v1(1160.14,4925.97) ; C11.1@1410.14,5003.47 v1(1472.64,5003.47) 1493.78,4982.32 U1.1@1510.14,4982.32
NetC12_1: C12.1 R12.2 U1.2 | length 987
  Signal Layer 1 w25: v1(1060.14,4863.47) 1060.14,4888.47 1233.96,5062.28 v1(1536.32,5062.28)
  Bottom Layer w25: R12.2@982.21,4863.47 v1(1060.14,4863.47) ; C12.1@1335.14,5003.47 1335.14,5038.47 1358.96,5062.28 v1(1536.32,5062.28) 1560.14,5038.47 U1.2@1560.14,4982.32
NetC13_1: C13.1 C15.1 L1.1 T1.12 T1.13 | length 942.3
  Top Layer w100: T1.13@3360.14,4661.78 T1.12@3360.14,4511.78 3529.43,4511.78 3604.79,4436.42 3740.93,4436.42 C13.1@3886.71,4290.63
  Bottom Layer w100: C13.1@3886.71,4290.63 3901.1,4305.02 C15.1@3901.1,4458.79
NetC16_1: C16.1 R15.1 | length 124.6
  Top Layer w70: C16.1@3742.22,3650.97 3831.5,3650.97 R15.1@3856.5,3625.97
NetC16_2: C16.2 Q3.5 Q3.6 Q3.7 Q3.8 Q3.9 R19.2 T1.9 T1.10 | length 1319.7
  Top Layer w30: v1(3772.64,3763.47) 3806.93,3763.47 3810.98,3759.41 ; Q3.8@3823.8,3772.23 Q3.7@3823.8,3824.39
  Top Layer w40: 3810.98,3759.41 Q3.8@3823.8,3772.23
  Top Layer w50: C16.2@3628.05,3650.97 3628.05,3767.36
  Top Layer w100: T1.10@3360.14,4211.78 T1.9@3360.14,4061.78 3381.43,4040.49 3595.61,4040.49 3758.56,3877.54 Q3.6@3823.8,3877.54
  Bottom Layer w30: v1(3772.64,3763.47) 3991.14,3544.96 R19.2@4085.14,3544.96
NetC21_1: C21.1 C22.2 | length 156.3
  Signal Layer 1 w70: C21.1@2771.85,3538.47 C22.2@2928.15,3538.47
NetC23_1: C23.1 R21.1 R22.2 U3.9 | length 224.5
  Bottom Layer w25: R21.1@472.64,4649.45 564.18,4649.45 565.7,4650.97 ; C23.1@553.64,4571.5 R22.2@553.64,4625.97 565.7,4638.03 565.7,4650.97 ; U3.9@565.7,4697.34 565.7,4650.97
NetC24_1: C24.1 U2.3 | length 139.3
  Bottom Layer w25: U2.3@4235.04,3567.6 4266.77,3567.6 4325.14,3625.97 C24.1@4325.14,3650.97
NetC25_1: C25.1 R24.1 U2.4 | length 179.6
  Bottom Layer w30: U2.4@4235.04,3459.33 4399.27,3459.33 R24.1@4410.14,3448.47
NetC26_1: C26.1 C28.1 R33.2 R35.2 U3.12 | length 2603.5
  Signal Layer 2 w40: v1(497.64,4847.34) 501.27,4850.97 585.14,4850.97 1047.64,5313.47 2435.14,5313.47 v1(2535.14,5213.47)
  Bottom Layer w25: C28.1@384.62,4878.77 R35.2@384.62,4839.17 ; U3.12@565.7,4847.34 v1(497.64,4847.34) 450.01,4847.34 C26.1@447.64,4844.96 390.4,4844.96 R35.2@384.62,4839.17 ; R35.2@384.62,4839.17 R35.2@384.62,4825.97 R35.2@384.62,4839.17
  Bottom Layer w40: v1(2535.14,5213.47) R33.2@2616.14,5213.47
NetC26_2: C26.2 C31.1 R25.1 R27.1 U3.16 | length 718.2
  Signal Layer 2 w25: v1(347.64,4782.46) 356.52,4782.46 497.64,4923.58 v1(497.64,5047.34)
  Bottom Layer w25: v1(347.64,4782.46) 348.13,4781.97 C26.2@447.64,4781.97 ; R27.1@385.14,5103.46 441.51,5103.46 v1(497.64,5047.34) U3.16@565.7,5047.34 565.7,5117.9 C31.1@557.64,5125.97
NetC27_2: C27.2 DZ1.1 Q4.1 R26.2 U3.8 | length 405.6
  Bottom Layer w25: U3.8@781,4696.6 U3.8@780.27,4697.34 780.27,4634.27 792.52,4622.02 DZ1.1@792.52,4541.77 792.52,4409.63 814.49,4387.65 R26.2@814.49,4363.47 814.49,4308.97 Q4.1@813.08,4307.56
NetC29_1: C29.1 R28.1 | length 62.2
  Bottom Layer w30: C29.1@3479.13,5120.22 3479.54,5120.63 R28.1@3541.14,5120.63
NetC29_2: C29.2 R31.1 U4.1 | length 486.5
  Bottom Layer w25: C29.2@3416.14,5120.22 3416.14,5075.97 3435.33,5056.78 R31.1@3478.64,5056.78
  Bottom Layer w30: U4.1@3128.25,5213.47 3400.21,5213.47 3416.14,5197.53 C29.2@3416.14,5120.22
NetC30_1: C30.1 C33.1 R32.1 R41.2 U5.2 | length 370.2
  Bottom Layer w25: R32.1@3704.13,5120.22 3704.13,5168 3718.41,5182.28 3791.22,5182.28 ; U5.2@3829.23,5182.28 3791.22,5182.28 ; C30.1@3839.64,5056.78 3787.64,5056.78 3772.64,5071.78 C33.1@3772.64,5120.63 3772.64,5163.7 3791.22,5182.28
NetC30_2: C30.2 D10.1 R30.1 R36.1 U4.2 U5.1 | length 1403.2
  Signal Layer 2 w30: v1(3197.64,5115.26) 3895.85,5115.26 v1(3985.14,5025.97)
  Bottom Layer w25: R30.1@3898.13,4988.91 3902.63,4993.41 C30.2@3902.63,5056.78 3958.18,5056.78 3959.06,5057.65 ; U5.1@3904.04,5182.28 3964.63,5182.28 3977.63,5169.28 R36.1@3977.63,5120.63 3977.63,5076.23 3959.06,5057.65 ; D10.1@4047.89,5057.65 3959.06,5057.65
  Bottom Layer w30: U4.2@3129.23,5113.47 3195.85,5113.47 v1(3197.64,5115.26) ; C30.2@3902.63,5038.47 3972.64,5038.47 ; v1(3985.14,5025.97) 3985.14,5051.91
NetC33_2: C33.2 R36.2 | length 79
  Bottom Layer w25: C33.2@3835.63,5120.63 R36.2@3914.64,5120.63
NetC36_1: C36.1 Dz2.1 R34.1 U3.7 | length 498.4
  Bottom Layer w25: U3.7@780.27,4747.34 829.82,4747.34 997.64,4579.51 Dz2.1@997.64,4527.8 997.64,4504.33 955.76,4462.46 R34.1@955.76,4385.39
NetC37_1: C37.1 R27.2 R39.2 U3.15 | length 326.3
  Bottom Layer w25: C37.1@260.14,5033.59 267.02,5040.47 R39.2@323.14,5040.47 R27.2@385.14,5040.47 411.64,5040.47 454.78,4997.34 U3.15@565.7,4997.34
NetC38_1: C38.1 R29.2 U3.3 | length 203.1
  Bottom Layer w25: U3.3@780.27,4947.34 821.51,4947.34 863.09,4988.91 C38.1@903.09,4988.91 R29.2@966.14,4988.91
NetC39_1: C39.1 D10.3 R42.2 | length 230.2
  Bottom Layer w30: 4123.71,5126.69 4142.37,5108.02 D10.3@4142.37,5095.06 ; R42.2@4123.71,5217.77 4155.97,5185.51 C39.1@4210.14,5185.51
  Bottom Layer w50: 4123.71,5126.69 R42.2@4123.71,5217.77
NetC100_1: C100.1 C101.1 C102.1 D100.2 F100.1 L100.4 L100.5 R102.2 | length 5976.6
  Top Layer w40: v2(1290.61,1193.19) 1290.61,1099.08 1408.63,981.06 C102.1@1550,981.06 ccw(c1550,951.97) 1520.9,951.97 v2(1520.9,900)
  Top Layer w150: C100.1@378.63,1064.86 C100.1@390.18,1064.86 ; D100.2@1319.95,2676.26 1368.69,2725 2342.9,2725 2906.57,2158.43 L100.4@2906.57,1658.23 ; v2(1520.9,900) v2(1675,900) ; L100.5@3103.42,1633.43 L100.5@3103.42,1658.23
  Top Layer w200: F100.1@131.25,817.48 350,1037.5 ; L100.4@2931.62,1633.43 3103.42,1633.43 L100.5@3128.47,1633.43
  Signal Layer 1 w30: 1275.16,1028.55 1392.36,1028.55 v2(1520.9,900)
  Signal Layer 1 w150: C101.1@1083.46,1027.98 1095.89,1028.02 1275.16,1028.55 1556.18,1029.38 2187.5,1031.25 ; 2199.9,1040.67 2662.5,1503.27 ; 2675,1500 2742.08,1500 L100.4@2903.1,1661.02
  Bottom Layer w30: v2(1290.61,1193.19) R102.2@1375,1193.19
NetC102_2: C102.2 C104.1 R102.1 R104.2 | length 263.2
  Top Layer w150: 1550,1231.25 1550,1300
  Bottom Layer w30: R102.1@1375,1307.37 1375,1349.26 R104.2@1375,1386.66 ; v2@1489.13,1349.26 v2(1489.87,1350)
  Bottom Layer w50: 1375,1349.26 v2@1489.13,1349.26
NetC103_2: C103.2 C106.1 R103.1 R106.2 | length 436.1
  Top Layer w50: 1137.87,1898.47 1278.62,1898.47 ; R106.2@1138.09,1807.09 1138.09,1981.32 R103.1@1143.75,1986.98 ; C106.1@1310.28,1838.53 1310.28,1945.81 C103.2@1314.45,1949.97
NetC109_1: C109.1 R114.1 | length 59.1
  Bottom Layer w30: C109.1@1093.53,699.02 1093.65,698.89 R114.1@1152.61,698.89
NetC109_2: C109.2 Q100.2 | length 82.7
  Bottom Layer w30: C109.2@1093.53,762.01 1106.12,774.61 Q100.2@1106.12,839.52
NetC110_1: C110.1 C111.1 Q102.2 R115.2 U100.1 | length 262.4
  Bottom Layer w25: Q102.2@1430.93,352.54 1430.93,407.6 C110.1@1431.27,407.95 1431.03,408.19 C111.1@1431.03,467.77 1446.05,482.8 U100.1@1499.54,482.8 1481.03,464.29 R115.2@1481.03,418.26
NetC110_2: C110.2 R121.2 | length 59.9
  Bottom Layer w25: C110.2@1368.28,407.95 1368.28,467.52 R121.2@1368.53,467.77
NetC112_1: C112.1 Q100.1 R111.1 U100.4 | length 725.1
  Signal Layer 2 w30: v1(1174.78,773.65) 1174.78,698.62 1238.48,634.92 1549.73,634.92 ccw(c1549.73,637.1) v1(1551.91,637.05)
  Bottom Layer w30: v1(1174.78,773.65) 1180.93,779.8 Q100.1@1180.93,839.52 ; R111.1@1489.87,751.15 1499.54,741.48 U100.4@1499.54,632.8 1501.66,634.92 1549.78,634.92 ccw(c1549.78,637.05) v1(1551.91,637.05)
NetC114_1: C114.1 D103.1 Q102.1 R109.1 | length 194.1
  Bottom Layer w25: D103.1@1168.53,336.77 1184.3,352.54 Q102.1@1356.12,352.54
NetC115_1: C115.1 R114.2 R120.1 R124.1 R125.2 U100.3 | length 574.4
  Bottom Layer w30: R114.2@1152.61,635.9 1205.71,582.8 U100.3@1499.54,582.8 ; R125.2@1221.36,604.4 R120.1@1365.57,604.4 1368.67,601.3 C115.1@1425.57,601.3
NetC116_1: C116.1 C117.1 C118.1 R134.1 R135.1 R138.2 R142.2 U102.6 | length 2187.6
  Top Layer w25: C117.1@1176.03,159.69 1176.03,202.61 1214.37,240.94 C116.1@1226.62,240.94 1226.87,241.19 1226.87,288.93 U102.6@1247.74,309.79
  Top Layer w40: v1(1106.25,162.5) 1109.06,159.69 C117.1@1176.03,159.69 ; v1@1106.25,456.25 1206.25,556.25 R138.2@1370.99,556.25 ; R142.2@1645.62,125.15 1645.77,125 v1(1706.25,125)
  Top Layer w50: v1(1706.25,125) 1756.45,74.8 2100,74.8 ; R135.1@2160,83.12 2151.68,74.8 2100,74.8 ; R134.1@2175,179.04 2135.04,179.04 2100,144 2100,74.8
  Signal Layer 1 w40: v1(1106.25,162.5) v1(1106.25,456.69)
  Signal Layer 2 w40: v1(1106.25,162.5) 1126.12,182.37 1393.59,182.37 1399.84,176.12 1655.13,176.12 v1(1706.25,125)
NetC121_1: C121.1 R145.1 R148.2 R151.2 R152.2 U102.1 | length 397.4
  Top Layer w25: U102.1@1356,309.79 1375,290.8 R152.2@1375,245.96
  Top Layer w30: U102.1@1350,302.89 C121.1@1482.87,303.44 ; R152.2@1383.12,245.37 R152.2@1383.12,245.96 ; R151.2@1464.37,211.91 1464.37,284.94 C121.1@1482.87,303.44 ; R145.1@1568.12,284.69 1555.87,296.95 C121.1@1489.37,296.95 C121.1@1482.87,303.44
NetC123_1: C123.1 R141.1 R144.1 R149.2 R152.1 | length 1340.4
  Top Layer w25: v1(1375,137.5) R152.1@1375,179.04 ; R141.1@1493.75,501.3 1488.04,495.59 R144.1@1488.04,434.69 1557.87,434.69 R149.2@1564.37,441.19 1564.37,514.37 1588.63,538.63 C123.1@1637.5,538.63 ; C123.1@1637.5,543.23 C123.1@1637.5,538.63 ; v1(1768.75,643.75) 1768.75,568.75 1733.25,533.25 1637.5,533.25 C123.1@1637.5,538.63
  Signal Layer 1 w25: v1(1375,137.5) 1535.88,137.5 1768.75,370.37 v1(1768.75,643.75)
NetC124_1: C124.1 R140.1 R147.1 R150.2 R151.1 | length 1747.5
  Top Layer w25: R147.1@1107.87,390.94 1024.66,390.94 C124.1@1020.62,386.91 926.58,386.91 R150.2@920.62,380.94 890.88,380.94 856.25,346.32 856.25,87.5 906.25,37.5 1418.75,37.5 1464.37,83.12 R151.1@1464.37,144.98
  Top Layer w50: R140.1@537.5,563.34 824.16,563.34 920.62,466.88 R150.2@920.62,380.94
NetD1_1: D1.1 R3.2 | length 472.6
  Bottom Layer w40: R3.2@1199.81,4840.97 1199.81,4864.4 1235.14,4899.72 1235.14,5042.08 1381.52,5188.47 D1.1@1431.4,5188.47
NetD2_1: D2.1 R6.2 U1.7 | length 633.6
  Bottom Layer w25: 1560.14,4688.47 U1.7@1560.14,4767.75
  Bottom Layer w50: D2.1@1536.32,4288.24 1551.54,4303.47 R6.2@1658.54,4303.47 1658.54,4361 1560.14,4459.41 1560.14,4688.47
NetD2_2: D2.2 Q1.1 R5.2 R6.1 | length 618.2
  Bottom Layer w50: R5.2@1587.64,3788.47 1635.93,3788.47 1660.14,3812.67 Q1.1@1660.14,3925.97
  Bottom Layer w70: D2.2@1536.32,4130.76 1653.74,4130.76 1658.54,4125.97 ; R6.1@1658.54,4223.47 1658.54,4125.97 ; Q1.1@1660.14,3925.97 1658.54,3927.56 1658.54,4125.97
NetD5_1: D5.1 R7.2 U1.5 | length 397
  Bottom Layer w50: 1674.41,4758.4 1707.64,4725.18 R7.2@1707.64,4512.54 1707.64,4444.12 D5.1@1756.4,4395.36
NetD5_2: D5.2 Q2.1 R7.1 R8.2 | length 414.3
  Bottom Layer w50: R7.1@1787.64,4512.54 1921.71,4512.54 Q2.1@1922.64,4513.47 ; D5.2@1913.88,4395.36 1922.64,4404.12 Q2.1@1922.64,4513.47 ; R8.2@2060.14,4560.97 2012.64,4513.47 Q2.1@1922.64,4513.47
NetD6_1: D6.1 R16.2 | length 157.4
  Bottom Layer w50: D6.1@2225,4968.72 2225,5008.09 2250,5033.09 R16.2@2332.69,5033.09
NetD6_2: D6.2 D7.2 D8.2 R21.2 T1.1 | length 2908.3
  Top Layer w70: D8.2@2276.38,5062.28 2358.45,4980.21 T1.1@2358.45,4827.89
  Signal Layer 2 w40: v1(479.2,4547.58) 488.35,4547.58 501.18,4560.41 497.64,4563.96 1159.65,5225.97 1889.01,5225.97 2287.09,4827.89 2344.03,4827.89 T1.1@2360.14,4811.78
  Bottom Layer w40: R21.2@472.64,4586.45 472.64,4554.15 v1(479.2,4547.58)
  Bottom Layer w50: D6.2@2225,4811.24 2225,4811.78 T1.1@2360.14,4811.78 2360.14,4918.26 ccw(c2350.2,4918.26) D7.2@2350.2,4928.2
NetD7_1: D7.1 R17.2 | length 127.7
  Bottom Layer w50: D7.1@2507.68,4928.2 2550,4885.88 R17.2@2550,4818.05
NetD8_1: D8.1 R20.2 | length 190.3
  Top Layer w70: R20.2@2100.14,5244.86 2118.9,5226.1 D8.1@2118.9,5062.28
NetD101_2: D101.2 L100.2 L100.3 Q101.2 | length 1898.3
  Top Layer w70: Q101.2@2868.75,1145.03 2868.75,1281.25
  Top Layer w150: D101.2@1872.22,2514.25 1954.5,2514.25 2316.01,2152.74 2316.01,1658.23 L100.3@2510.29,1658.23 ; L100.3@2509.4,1659.14 L100.3@2510.29,1658.23 ; L100.3@2512.87,1658.23 L100.3@2510.29,1658.23 ; 2843.75,1318.75 L100.3@2510.29,1658.23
